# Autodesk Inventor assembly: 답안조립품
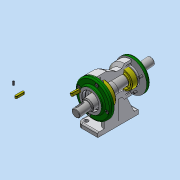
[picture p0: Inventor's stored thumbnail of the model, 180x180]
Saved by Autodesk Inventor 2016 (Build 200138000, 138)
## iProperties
Created: 2019-01
Part Number: 답안조립품
Material: 일반
Document SubType Name: Assembly
Designer: Administrator
Author: Administrator
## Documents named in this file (11)
- C:\Users\Administrator\Desktop\490108V1006\답안조립품.iam
- C:\Users\Administrator\Desktop\490108V1006\본체.ipt
- C:\Users\Administrator\Desktop\490108V1006\베어링 6205.ipt
- C:\Users\Administrator\Desktop\490108V1006\앞커버.ipt
- C:\Users\Administrator\Desktop\490108V1006\볼트 M4.ipt
- C:\Users\Administrator\Desktop\490108V1006\뒤커버.ipt
- C:\Users\Administrator\Desktop\490108V1006\베어링 6203.ipt
- C:\Users\Administrator\Desktop\490108V1006\축.ipt
- C:\Users\Administrator\Desktop\490108V1006\키 6 x 6 x 18.ipt
- C:\Users\Administrator\Desktop\490108V1006\멈춤나사 M3.ipt
- C:\Users\Administrator\Desktop\490108V1006\키 5 x 5 x 20.ipt
